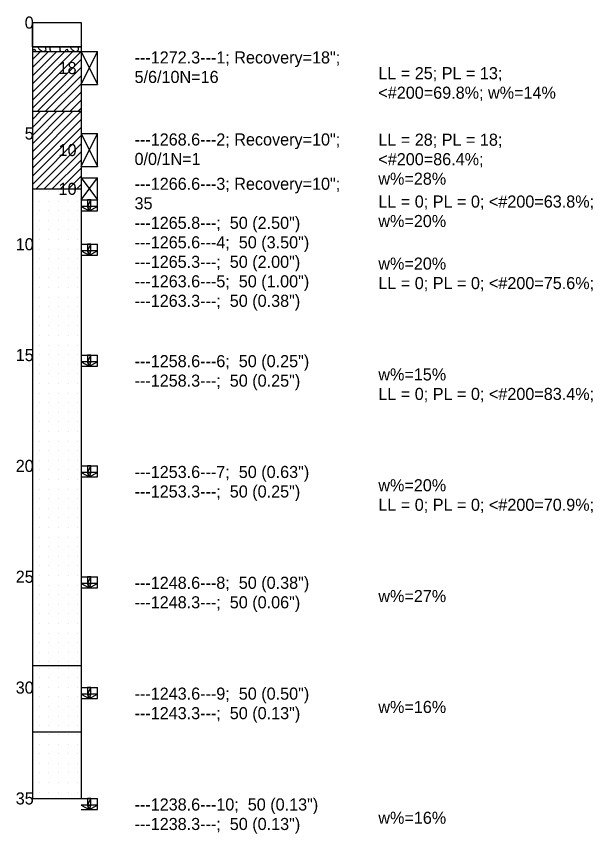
# Model space of a CAD drawing. Extents: x 2150161.5 to 2150203.1, y 143779.5 to 143868.5.
# Drawn here: x 2150176.41 to 2150182.32, y 143847.49 to 143855.87 of the extents above; entities that cross this region are included whole.
import ezdxf

# ---------------------------------------------------------------- set-up
doc = ezdxf.new("R2010")
doc.units = 0
doc.layers.add('Default', color=7, linetype='Continuous')

# ---------------------------------------------------------------- blocks, each defined once
blk = doc.blocks.new('POINT_DISPLAY')
at = {"layer": 'Default'}
blk.add_line((0, 0), (0, 0), dxfattribs=at)

msp = doc.modelspace()

# ---------------------------------------------------------------- linework, layer by layer
at = {"layer": 'Default'}
for points in [[(2150176.5731, 143855.5548), (2150176.5731, 143855.8048), (2150177.0731, 143855.8048), (2150177.0731, 143855.5548)], [(2150177.1398, 143853.9184), (2150177.0731, 143853.9184), (2150177.1564, 143853.8729), (2150177.1398, 143853.9184)], [(2150177.1398, 143853.9184), (2150177.1731, 143853.9184), (2150177.1731, 143853.9866), (2150177.1398, 143853.9184)], [(2150177.1398, 143853.9184), (2150177.1731, 143853.9866), (2150177.1398, 143853.9866), (2150177.1398, 143853.9184)], [(2150177.1398, 143853.9184), (2150177.1564, 143853.8729), (2150177.1731, 143853.9184), (2150177.1398, 143853.9184)], [(2150177.1564, 143853.8729), (2150177.2398, 143853.9184), (2150177.1731, 143853.9184), (2150177.1564, 143853.8729)], [(2150177.1398, 143853.4639), (2150177.1731, 143853.4639), (2150177.1731, 143853.532), (2150177.1398, 143853.4639)], [(2150177.1398, 143853.4639), (2150177.1731, 143853.532), (2150177.1398, 143853.532), (2150177.1398, 143853.4639)], [(2150177.1398, 143853.4639), (2150177.0731, 143853.4639), (2150177.1564, 143853.4184), (2150177.1398, 143853.4639)], [(2150177.1398, 143853.4639), (2150177.1564, 143853.4184), (2150177.1731, 143853.4639), (2150177.1398, 143853.4639)], [(2150177.1564, 143853.4184), (2150177.2398, 143853.4639), (2150177.1731, 143853.4639), (2150177.1564, 143853.4184)], [(2150177.1398, 143852.3275), (2150177.0731, 143852.3275), (2150177.1564, 143852.282), (2150177.1398, 143852.3275)], [(2150177.1398, 143852.3275), (2150177.1731, 143852.3275), (2150177.1731, 143852.3957), (2150177.1398, 143852.3275)], [(2150177.1398, 143852.3275), (2150177.1731, 143852.3957), (2150177.1398, 143852.3957), (2150177.1398, 143852.3275)], [(2150177.1398, 143852.3275), (2150177.1564, 143852.282), (2150177.1731, 143852.3275), (2150177.1398, 143852.3275)], [(2150177.1564, 143852.282), (2150177.2398, 143852.3275), (2150177.1731, 143852.3275), (2150177.1564, 143852.282)], [(2150177.1398, 143851.1911), (2150177.1731, 143851.1911), (2150177.1731, 143851.2593), (2150177.1398, 143851.1911)], [(2150177.1398, 143851.1911), (2150177.1731, 143851.2593), (2150177.1398, 143851.2593), (2150177.1398, 143851.1911)], [(2150177.1398, 143851.1911), (2150177.0731, 143851.1911), (2150177.1564, 143851.1457), (2150177.1398, 143851.1911)], [(2150177.1398, 143851.1911), (2150177.1564, 143851.1457), (2150177.1731, 143851.1911), (2150177.1398, 143851.1911)], [(2150177.1564, 143851.1457), (2150177.2398, 143851.1911), (2150177.1731, 143851.1911), (2150177.1564, 143851.1457)], [(2150177.1398, 143850.0548), (2150177.0731, 143850.0548), (2150177.1564, 143850.0093), (2150177.1398, 143850.0548)], [(2150177.1398, 143850.0548), (2150177.1731, 143850.0548), (2150177.1731, 143850.123), (2150177.1398, 143850.0548)], [(2150177.1398, 143850.0548), (2150177.1731, 143850.123), (2150177.1398, 143850.123), (2150177.1398, 143850.0548)], [(2150177.1398, 143850.0548), (2150177.1564, 143850.0093), (2150177.1731, 143850.0548), (2150177.1398, 143850.0548)], [(2150177.1564, 143850.0093), (2150177.2398, 143850.0548), (2150177.1731, 143850.0548), (2150177.1564, 143850.0093)], [(2150177.1398, 143848.9184), (2150177.1731, 143848.9184), (2150177.1731, 143848.9866), (2150177.1398, 143848.9184)], [(2150177.1398, 143848.9184), (2150177.1731, 143848.9866), (2150177.1398, 143848.9866), (2150177.1398, 143848.9184)], [(2150177.1398, 143848.9184), (2150177.0731, 143848.9184), (2150177.1564, 143848.873), (2150177.1398, 143848.9184)], [(2150177.1398, 143848.9184), (2150177.1564, 143848.873), (2150177.1731, 143848.9184), (2150177.1398, 143848.9184)], [(2150177.1564, 143848.873), (2150177.2398, 143848.9184), (2150177.1731, 143848.9184), (2150177.1564, 143848.873)], [(2150177.1398, 143847.782), (2150177.1731, 143847.782), (2150177.1731, 143847.8502), (2150177.1398, 143847.782)], [(2150177.1398, 143847.782), (2150177.1731, 143847.8502), (2150177.1398, 143847.8502), (2150177.1398, 143847.782)], [(2150177.1398, 143847.782), (2150177.0731, 143847.782), (2150177.1564, 143847.7366), (2150177.1398, 143847.782)], [(2150177.1398, 143847.782), (2150177.1564, 143847.7366), (2150177.1731, 143847.782), (2150177.1398, 143847.782)], [(2150177.1564, 143847.7366), (2150177.2398, 143847.782), (2150177.1731, 143847.782), (2150177.1564, 143847.7366)]]:
    msp.add_lwpolyline(points, close=True, dxfattribs=at)
for points in [[(2150176.5731, 143855.8048), (2150176.5731, 143847.8502)], [(2150177.0731, 143855.8048), (2150177.0731, 143847.8502)], [(2150176.5731, 143855.5548), (2150177.0731, 143855.5548)], [(2150176.5731, 143855.5093), (2150177.0731, 143855.5093)], [(2150176.5731, 143855.426), (2150176.6564, 143855.5093)], [(2150176.5731, 143855.3426), (2150176.7398, 143855.5093)], [(2150176.5731, 143855.2593), (2150176.8231, 143855.5093)], [(2150176.5731, 143855.176), (2150176.9064, 143855.5093)], [(2150176.5731, 143855.0926), (2150176.9898, 143855.5093)], [(2150176.5731, 143855.0093), (2150177.0731, 143855.5093)], [(2150176.6081, 143855.5131), (2150176.5998, 143855.5281), (2150176.5864, 143855.5239), (2150176.5764, 143855.5148), (2150176.5781, 143855.5093), (2150176.6081, 143855.5093), (2150176.6081, 143855.5131)], [(2150176.673, 143855.5093), (2150176.6639, 143855.5156), (2150176.6523, 143855.5231), (2150176.6414, 143855.5306), (2150176.6348, 143855.5448), (2150176.6348, 143855.5492), (2150176.6348, 143855.5548)], [(2150176.709, 143855.5548), (2150176.7093, 143855.5424), (2150176.7098, 143855.5231), (2150176.7039, 143855.5156), (2150176.6926, 143855.5093)], [(2150176.7617, 143855.5093), (2150176.7614, 143855.5098), (2150176.7548, 143855.5298), (2150176.7556, 143855.5382), (2150176.7573, 143855.5548)], [(2150176.8498, 143855.5548), (2150176.8539, 143855.5439), (2150176.8548, 143855.5331), (2150176.855, 143855.5291), (2150176.8556, 143855.5198), (2150176.8616, 143855.5093)], [(2150176.9414, 143855.5131), (2150176.9331, 143855.5281), (2150176.9198, 143855.5239), (2150176.9098, 143855.5148), (2150176.9115, 143855.5093), (2150176.9414, 143855.5093), (2150176.9414, 143855.5131)], [(2150177.0064, 143855.5093), (2150176.9973, 143855.5156), (2150176.9962, 143855.5163), (2150176.9856, 143855.5231), (2150176.9748, 143855.5306), (2150176.9681, 143855.5448), (2150176.9681, 143855.5548)], [(2150177.0423, 143855.5548), (2150177.0431, 143855.5231), (2150177.0373, 143855.5156), (2150177.0326, 143855.513), (2150177.026, 143855.5093)], [(2150177.0731, 143855.5093), (2150177.2398, 143855.1684)], [(2150177.0731, 143855.1684), (2150177.2398, 143855.5093)], [(2150177.0731, 143855.5093), (2150177.2398, 143855.5093)], [(2150177.2398, 143855.1684), (2150177.2398, 143855.5093)], [(2150176.5731, 143854.926), (2150177.0731, 143855.426)], [(2150176.6261, 143854.8957), (2150177.0731, 143855.3426)], [(2150176.7095, 143854.8957), (2150177.0731, 143855.2593)], [(2150176.7928, 143854.8957), (2150177.0731, 143855.176)], [(2150177.0731, 143855.1684), (2150177.2398, 143855.1684)], [(2150176.8761, 143854.8957), (2150177.0731, 143855.0926)], [(2150176.9595, 143854.8957), (2150177.0731, 143855.0093)], [(2150177.0428, 143854.8957), (2150177.0731, 143854.926)], [(2150176.5731, 143854.8957), (2150177.0731, 143854.8957)], [(2150176.5731, 143854.8123), (2150176.6564, 143854.8957)], [(2150176.5731, 143854.729), (2150176.7398, 143854.8957)], [(2150176.5731, 143854.6457), (2150176.8231, 143854.8957)], [(2150176.5731, 143854.5623), (2150176.9064, 143854.8957)], [(2150176.5731, 143854.479), (2150176.9898, 143854.8957)], [(2150176.5731, 143854.3957), (2150177.0731, 143854.8957)], [(2150176.5731, 143854.3123), (2150177.0731, 143854.8123)], [(2150176.5731, 143854.229), (2150177.0731, 143854.729)], [(2150177.0731, 143854.6684), (2150177.2398, 143854.3275)], [(2150177.0731, 143854.3275), (2150177.2398, 143854.6684)], [(2150177.0731, 143854.6684), (2150177.2398, 143854.6684)], [(2150177.2398, 143854.3275), (2150177.2398, 143854.6684)], [(2150176.5731, 143854.1457), (2150177.0731, 143854.6457)], [(2150176.611, 143854.1002), (2150177.0731, 143854.5623)], [(2150176.6943, 143854.1002), (2150177.0731, 143854.479)], [(2150176.7777, 143854.1002), (2150177.0731, 143854.3957)], [(2150177.0731, 143854.3275), (2150177.2398, 143854.3275)], [(2150176.861, 143854.1002), (2150177.0731, 143854.3123)], [(2150176.9443, 143854.1002), (2150177.0731, 143854.229)], [(2150177.0731, 143854.2139), (2150177.2398, 143853.9866)], [(2150177.0731, 143853.9866), (2150177.2398, 143854.2139)], [(2150177.0731, 143854.2139), (2150177.2398, 143854.2139)], [(2150177.2398, 143853.9866), (2150177.2398, 143854.2139)], [(2150176.5731, 143854.1002), (2150177.0731, 143854.1002)], [(2150177.0277, 143854.1002), (2150177.0731, 143854.1457)], [(2150177.0731, 143853.9866), (2150177.2398, 143853.9866)], [(2150177.0731, 143853.9866), (2150177.2398, 143853.9866)], [(2150177.2398, 143853.8729), (2150177.2398, 143853.9866)], [(2150177.0731, 143853.8729), (2150177.2398, 143853.8729)], [(2150177.0731, 143853.532), (2150177.2398, 143853.532)], [(2150177.2398, 143853.4184), (2150177.2398, 143853.532)], [(2150177.0731, 143853.4184), (2150177.2398, 143853.4184)], [(2150177.0731, 143852.3957), (2150177.2398, 143852.3957)], [(2150177.2398, 143852.282), (2150177.2398, 143852.3957)], [(2150177.0731, 143852.282), (2150177.2398, 143852.282)], [(2150177.0731, 143851.2593), (2150177.2398, 143851.2593)], [(2150177.2398, 143851.1457), (2150177.2398, 143851.2593)], [(2150177.0731, 143851.1457), (2150177.2398, 143851.1457)], [(2150177.0731, 143850.123), (2150177.2398, 143850.123)], [(2150177.2398, 143850.0093), (2150177.2398, 143850.123)], [(2150177.0731, 143850.0093), (2150177.2398, 143850.0093)], [(2150176.5731, 143849.2139), (2150177.0731, 143849.2139)], [(2150177.0731, 143848.9866), (2150177.2398, 143848.9866)], [(2150177.2398, 143848.873), (2150177.2398, 143848.9866)], [(2150177.0731, 143848.873), (2150177.2398, 143848.873)], [(2150176.5731, 143848.532), (2150177.0731, 143848.532)], [(2150176.5731, 143847.8502), (2150177.0731, 143847.8502)], [(2150177.0731, 143847.8502), (2150177.2398, 143847.8502)], [(2150177.2398, 143847.7366), (2150177.2398, 143847.8502)], [(2150177.0731, 143847.7366), (2150177.2398, 143847.7366)]]:
    msp.add_lwpolyline(points, dxfattribs=at)

# ---------------------------------------------------------------- block references
at = {"layer": 'Default', "xscale": 0.39369999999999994, "yscale": 0.3936999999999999}
for p in [(2150176.5789, 143855.426), (2150176.6123, 143855.4926), (2150176.6789, 143855.4593), (2150176.7789, 143855.4926), (2150176.8019, 143855.429), (2150176.8789, 143855.4593), (2150176.9986, 143855.476), (2150177.0456, 143855.426), (2150176.6456, 143855.3926), (2150176.7123, 143855.3593), (2150176.8456, 143855.3926), (2150176.9456, 143855.3926), (2150176.6123, 143855.326), (2150176.6456, 143855.2593), (2150176.7789, 143855.2926), (2150176.8624, 143855.3169), (2150176.8789, 143855.2593), (2150177.0123, 143855.326), (2150176.5789, 143855.1926), (2150176.7123, 143855.226), (2150176.7973, 143855.2154), (2150176.9971, 143855.2411), (2150177.0456, 143855.1926), (2150176.6789, 143855.1593), (2150176.7456, 143855.126), (2150176.8123, 143855.0926), (2150176.8488, 143855.1457), (2150176.9123, 143855.1593), (2150176.9789, 143855.126), (2150176.6456, 143855.0593), (2150176.7789, 143855.026), (2150176.8912, 143855.0593), (2150177.0123, 143855.0593), (2150176.5789, 143854.9926), (2150176.6123, 143854.926), (2150176.6789, 143854.9593), (2150176.8456, 143854.9593), (2150176.9456, 143854.9926), (2150177.0123, 143854.926), (2150176.6443, 143854.073), (2150176.7427, 143854.073), (2150176.8411, 143854.073), (2150176.9396, 143854.073), (2150177.038, 143854.073), (2150176.6443, 143853.9745), (2150176.7427, 143853.9745), (2150176.8411, 143853.9745), (2150176.9396, 143853.9745), (2150177.038, 143853.9745), (2150176.6443, 143853.8761), (2150176.7427, 143853.8761), (2150176.8411, 143853.8761), (2150176.9396, 143853.8761), (2150177.038, 143853.8761), (2150176.6443, 143853.7777), (2150176.7427, 143853.7777), (2150176.8411, 143853.7777), (2150176.9396, 143853.7777), (2150177.038, 143853.7777), (2150176.6443, 143853.6793), (2150176.7427, 143853.6793), (2150176.8411, 143853.6793), (2150176.9396, 143853.6793), (2150177.038, 143853.6793), (2150176.6443, 143853.5808), (2150176.7427, 143853.5808), (2150176.8411, 143853.5808), (2150176.9396, 143853.5808), (2150177.038, 143853.5808), (2150176.6443, 143853.4824), (2150176.7427, 143853.4824), (2150176.8411, 143853.4824), (2150176.9396, 143853.4824), (2150177.038, 143853.4824), (2150176.6443, 143853.384), (2150176.7427, 143853.384), (2150176.8411, 143853.384), (2150176.9396, 143853.384), (2150177.038, 143853.384), (2150176.6443, 143853.2856), (2150176.7427, 143853.2856), (2150176.8411, 143853.2856), (2150176.9396, 143853.2856), (2150177.038, 143853.2856), (2150176.6443, 143853.1871), (2150176.7427, 143853.1871), (2150176.8411, 143853.1871), (2150176.9396, 143853.1871), (2150177.038, 143853.1871), (2150176.6443, 143853.0887), (2150176.7427, 143853.0887), (2150176.8411, 143853.0887), (2150176.9396, 143853.0887), (2150177.038, 143853.0887), (2150176.6443, 143852.9903), (2150176.7427, 143852.9903), (2150176.8411, 143852.9903), (2150176.9396, 143852.9903), (2150177.038, 143852.9903), (2150176.6443, 143852.8919), (2150176.7427, 143852.8919), (2150176.8411, 143852.8919), (2150176.9396, 143852.8919), (2150177.038, 143852.8919), (2150176.6443, 143852.7934), (2150176.7427, 143852.7934), (2150176.8411, 143852.7934), (2150176.9396, 143852.7934), (2150177.038, 143852.7934), (2150176.6443, 143852.695), (2150176.7427, 143852.695), (2150176.8411, 143852.695), (2150176.9396, 143852.695), (2150177.038, 143852.695), (2150176.6443, 143852.5966), (2150176.7427, 143852.5966), (2150176.8411, 143852.5966), (2150176.9396, 143852.5966), (2150177.038, 143852.5966), (2150176.6443, 143852.4982), (2150176.7427, 143852.4982), (2150176.8411, 143852.4982), (2150176.9396, 143852.4982), (2150177.038, 143852.4982), (2150176.6443, 143852.3997), (2150176.7427, 143852.3997), (2150176.8411, 143852.3997), (2150176.9396, 143852.3997), (2150177.038, 143852.3997), (2150176.6443, 143852.3013), (2150176.7427, 143852.3013), (2150176.8411, 143852.3013), (2150176.9396, 143852.3013), (2150177.038, 143852.3013), (2150176.6443, 143852.2029), (2150176.7427, 143852.2029), (2150176.8411, 143852.2029), (2150176.9396, 143852.2029), (2150177.038, 143852.2029), (2150176.6443, 143852.1045), (2150176.7427, 143852.1045), (2150176.8411, 143852.1045), (2150176.9396, 143852.1045), (2150177.038, 143852.1045), (2150176.6443, 143852.006), (2150176.7427, 143852.006), (2150176.8411, 143852.006), (2150176.9396, 143852.006), (2150177.038, 143852.006), (2150176.6443, 143851.9076), (2150176.7427, 143851.9076), (2150176.8411, 143851.9076), (2150176.9396, 143851.9076), (2150177.038, 143851.9076), (2150176.6443, 143851.8092), (2150176.7427, 143851.8092), (2150176.8411, 143851.8092), (2150176.9396, 143851.8092), (2150177.038, 143851.8092), (2150176.6443, 143851.7108), (2150176.7427, 143851.7108), (2150176.8411, 143851.7108), (2150176.9396, 143851.7108), (2150177.038, 143851.7108), (2150176.6443, 143851.6123), (2150176.7427, 143851.6123), (2150176.8411, 143851.6123), (2150176.9396, 143851.6123), (2150177.038, 143851.6123), (2150176.6443, 143851.5139), (2150176.7427, 143851.5139), (2150176.8411, 143851.5139), (2150176.9396, 143851.5139), (2150177.038, 143851.5139), (2150176.6443, 143851.4155), (2150176.7427, 143851.4155), (2150176.8411, 143851.4155), (2150176.9396, 143851.4155), (2150177.038, 143851.4155), (2150176.6443, 143851.3171), (2150176.7427, 143851.3171), (2150176.8411, 143851.3171), (2150176.9396, 143851.3171), (2150177.038, 143851.3171), (2150176.6443, 143851.2186), (2150176.7427, 143851.2186), (2150176.8411, 143851.2186), (2150176.9396, 143851.2186), (2150177.038, 143851.2186), (2150176.6443, 143851.1202), (2150176.7427, 143851.1202), (2150176.8411, 143851.1202), (2150176.9396, 143851.1202), (2150177.038, 143851.1202), (2150176.6443, 143851.0218), (2150176.7427, 143851.0218), (2150176.8411, 143851.0218), (2150176.9396, 143851.0218), (2150177.038, 143851.0218), (2150176.6443, 143850.9234), (2150176.7427, 143850.9234), (2150176.8411, 143850.9234), (2150176.9396, 143850.9234), (2150177.038, 143850.9234), (2150176.6443, 143850.8249), (2150176.7427, 143850.8249), (2150176.8411, 143850.8249), (2150176.9396, 143850.8249), (2150177.038, 143850.8249), (2150176.6443, 143850.7265), (2150176.7427, 143850.7265), (2150176.8411, 143850.7265), (2150176.9396, 143850.7265), (2150177.038, 143850.7265), (2150176.6443, 143850.6281), (2150176.7427, 143850.6281), (2150176.8411, 143850.6281), (2150176.9396, 143850.6281), (2150177.038, 143850.6281), (2150176.6443, 143850.5297), (2150176.7427, 143850.5297), (2150176.8411, 143850.5297), (2150176.9396, 143850.5297), (2150177.038, 143850.5297), (2150176.6443, 143850.4312), (2150176.7427, 143850.4312), (2150176.8411, 143850.4312), (2150176.9396, 143850.4312), (2150177.038, 143850.4312), (2150176.6443, 143850.3328), (2150176.7427, 143850.3328), (2150176.8411, 143850.3328), (2150176.9396, 143850.3328), (2150177.038, 143850.3328), (2150176.6443, 143850.2344), (2150176.7427, 143850.2344), (2150176.8411, 143850.2344), (2150176.9396, 143850.2344), (2150177.038, 143850.2344), (2150176.6443, 143850.136), (2150176.7427, 143850.136), (2150176.8411, 143850.136), (2150176.9396, 143850.136), (2150177.038, 143850.136), (2150176.6443, 143850.0375), (2150176.7427, 143850.0375), (2150176.8411, 143850.0375), (2150176.9396, 143850.0375), (2150177.038, 143850.0375), (2150176.6443, 143849.9391), (2150176.7427, 143849.9391), (2150176.8411, 143849.9391), (2150176.9396, 143849.9391), (2150177.038, 143849.9391), (2150176.6443, 143849.8407), (2150176.7427, 143849.8407), (2150176.8411, 143849.8407), (2150176.9396, 143849.8407), (2150177.038, 143849.8407), (2150176.6443, 143849.7423), (2150176.7427, 143849.7423), (2150176.8411, 143849.7423), (2150176.9396, 143849.7423), (2150177.038, 143849.7423), (2150176.6443, 143849.6438), (2150176.7427, 143849.6438), (2150176.8411, 143849.6438), (2150176.9396, 143849.6438), (2150177.038, 143849.6438), (2150176.6443, 143849.5454), (2150176.7427, 143849.5454), (2150176.8411, 143849.5454), (2150176.9396, 143849.5454), (2150177.038, 143849.5454), (2150176.6443, 143849.447), (2150176.7427, 143849.447), (2150176.8411, 143849.447), (2150176.9396, 143849.447), (2150177.038, 143849.447), (2150176.6443, 143849.3486), (2150176.7427, 143849.3486), (2150176.8411, 143849.3486), (2150176.9396, 143849.3486), (2150177.038, 143849.3486), (2150176.6443, 143849.2501), (2150176.7427, 143849.2501), (2150176.8411, 143849.2501), (2150176.9396, 143849.2501), (2150177.038, 143849.2501), (2150176.6443, 143849.1866), (2150176.7427, 143849.1866), (2150176.8411, 143849.1866), (2150176.9396, 143849.1866), (2150177.038, 143849.1866), (2150176.6443, 143849.0882), (2150176.7427, 143849.0882), (2150176.8411, 143849.0882), (2150176.9396, 143849.0882), (2150177.038, 143849.0882), (2150176.6443, 143848.9897), (2150176.7427, 143848.9897), (2150176.8411, 143848.9897), (2150176.9396, 143848.9897), (2150177.038, 143848.9897), (2150176.6443, 143848.8913), (2150176.7427, 143848.8913), (2150176.8411, 143848.8913), (2150176.9396, 143848.8913), (2150177.038, 143848.8913), (2150176.6443, 143848.7929), (2150176.7427, 143848.7929), (2150176.8411, 143848.7929), (2150176.9396, 143848.7929), (2150177.038, 143848.7929), (2150176.6443, 143848.6945), (2150176.7427, 143848.6945), (2150176.8411, 143848.6945), (2150176.9396, 143848.6945), (2150177.038, 143848.6945), (2150176.6443, 143848.596), (2150176.7427, 143848.596), (2150176.8411, 143848.596), (2150176.9396, 143848.596), (2150177.038, 143848.596), (2150176.6443, 143848.5048), (2150176.7427, 143848.5048), (2150176.8411, 143848.5048), (2150176.9396, 143848.5048), (2150177.038, 143848.5048), (2150176.6443, 143848.4064), (2150176.7427, 143848.4064), (2150176.8411, 143848.4064), (2150176.9396, 143848.4064), (2150177.038, 143848.4064), (2150176.6443, 143848.3079), (2150176.7427, 143848.3079), (2150176.8411, 143848.3079), (2150176.9396, 143848.3079), (2150177.038, 143848.3079), (2150176.6443, 143848.2095), (2150176.7427, 143848.2095), (2150176.8411, 143848.2095), (2150176.9396, 143848.2095), (2150177.038, 143848.2095), (2150176.6443, 143848.1111), (2150176.7427, 143848.1111), (2150176.8411, 143848.1111), (2150176.9396, 143848.1111), (2150177.038, 143848.1111), (2150176.6443, 143848.0127), (2150176.7427, 143848.0127), (2150176.8411, 143848.0127), (2150176.9396, 143848.0127), (2150177.038, 143848.0127), (2150176.6443, 143847.9142), (2150176.7427, 143847.9142), (2150176.8411, 143847.9142), (2150176.9396, 143847.9142), (2150177.038, 143847.9142)]:
    msp.add_blockref('POINT_DISPLAY', p, dxfattribs=at)

# ---------------------------------------------------------------- texts
at = {"layer": 'Default'}
for s, p in [('0', (2150176.4948, 143855.7428)), ('---1272.3---1; Recovery=18";', (2150177.6211, 143855.3853)), ('18', (2150176.8422, 143855.2769)), ('LL = 25; PL = 13;', (2150180.1211, 143855.2239)), ('5/6/10N=16', (2150177.6211, 143855.1853)), ('<#200=69.8%; w%=14%', (2150180.1211, 143855.0239)), ('5', (2150176.4948, 143854.6064)), ('---1268.6---2; Recovery=10";', (2150177.6211, 143854.5444)), ('LL = 28; PL = 18;', (2150180.1211, 143854.5421)), ('10', (2150176.8422, 143854.4359)), ('0/0/1N=1', (2150177.6211, 143854.3444)), ('<#200=86.4%;', (2150180.1211, 143854.3421)), ('w%=28%', (2150180.1211, 143854.1421)), ('10', (2150176.8422, 143854.0382)), ('---1266.6---3; Recovery=10";', (2150177.6211, 143854.0899)), ('35', (2150177.6211, 143853.8899)), ('LL = 0; PL = 0; <#200=63.8%;', (2150180.1211, 143853.908)), ('w%=20%', (2150180.1211, 143853.708)), ('---1265.8---;  50 (2.50")', (2150177.6211, 143853.6899)), ('10', (2150176.4027, 143853.47)), ('---1265.6---4;  50 (3.50")', (2150177.6211, 143853.4899)), ('---1265.3---;  50 (2.00")', (2150177.6211, 143853.2899)), ('w%=20%', (2150180.1211, 143853.2717)), ('---1263.6---5;  50 (1.00")', (2150177.6211, 143853.0899)), ('LL = 0; PL = 0; <#200=75.6%;', (2150180.1211, 143853.0717)), ('---1263.3---;  50 (0.38")', (2150177.6211, 143852.8899)), ('15', (2150176.4027, 143852.3337)), ('---1258.6---6;  50 (0.25")', (2150177.6211, 143852.2717)), ('w%=15%', (2150180.1211, 143852.1353)), ('---1258.3---;  50 (0.25")', (2150177.6211, 143852.0717)), ('LL = 0; PL = 0; <#200=83.4%;', (2150180.1211, 143851.9353)), ('20', (2150176.4027, 143851.1973)), ('---1253.6---7;  50 (0.63")', (2150177.6211, 143851.1353)), ('---1253.3---;  50 (0.25")', (2150177.6211, 143850.9353)), ('w%=20%', (2150180.1211, 143850.999)), ('LL = 0; PL = 0; <#200=70.9%;', (2150180.1211, 143850.799)), ('25', (2150176.4027, 143850.061)), ('---1248.6---8;  50 (0.38")', (2150177.6211, 143849.999)), ('w%=27%', (2150180.1211, 143849.8626)), ('---1248.3---;  50 (0.06")', (2150177.6211, 143849.799)), ('30', (2150176.4027, 143848.9246)), ('---1243.6---9;  50 (0.50")', (2150177.6211, 143848.8626)), ('w%=16%', (2150180.1211, 143848.7262)), ('---1243.3---;  50 (0.13")', (2150177.6211, 143848.6626)), ('35', (2150176.4027, 143847.7882)), ('---1238.6---10;  50 (0.13")', (2150177.6211, 143847.7262)), ('w%=16%', (2150180.1211, 143847.5899)), ('---1238.3---;  50 (0.13")', (2150177.6211, 143847.5262))]:
    msp.add_text(s, height=0.124, dxfattribs=at).set_placement(p)

doc.saveas('drawing.dxf')
